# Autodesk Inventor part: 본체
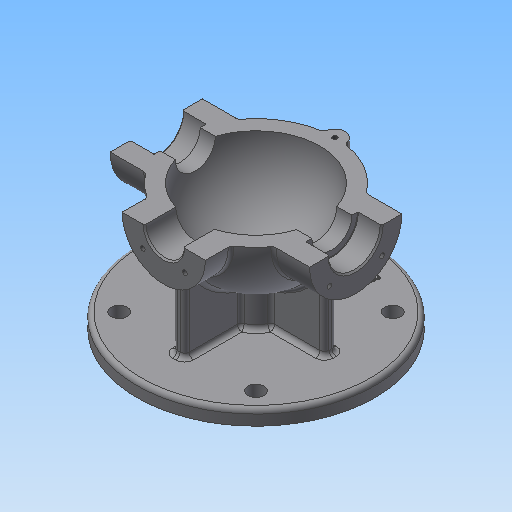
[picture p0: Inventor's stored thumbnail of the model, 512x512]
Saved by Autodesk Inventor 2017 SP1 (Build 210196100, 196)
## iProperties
Created: 2015-12
Part Number: 본체
Material: 일반
Document SubType Name: Modeling
Designer: mduedu
Density: 2.71 g/cm^3
Appearance: 기본값
Author: mduedu
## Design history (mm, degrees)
sketch "스케치1"
  geometry: L1 (-53, 0)-(53, 0); A1 r 53 centre (0, 0) between (53, 0) and (-53, 0); 2 further points
  constraints: 2 coincident, 2 end point, 2 point on circle, 1 centre point, 1 horizontal, 1 midpoint
  dimensions: "d0" = 53 radius of A1
revolve "회전1" sketch "스케치1" stored, may be unused: angle "d2" = 90 deg
feature "쉘1" dims "d11" = 10
node "작업 평면1"
sketch "스케치2"
  geometry: C1 r 31 at (0, 0); 1 further point
  constraints: 1 centre point, 1 coincident
  dimensions: "d4" = 62 diameter of C1
extrude "돌출1" join sketch "스케치2" stored distance "d5" = 10; taper "d6" = 0 deg
node "작업 평면2"
sketch "스케치3"
  geometry: C1 r 28 at (0, 0); 1 further point
  constraints: 1 centre point, 1 coincident
  dimensions: "d8" = 56 diameter of C1
extrude "돌출2" join sketch "스케치3" stored distance "d9" = 10; taper "d10" = 0 deg
hole "구멍1" diameter "d14" = 35; stored, may be unused: countersink angle "d18" = 90 deg, drill point angle "d20" = 0 deg; dims "d12" = 10, "d13" = 10, "d15" = 6, "d16" = 4, "d17" = 2, "d19" = 16
hole "구멍2" diameter "d23" = 27; stored, may be unused: countersink angle "d27" = 90 deg, drill point angle "d29" = 0 deg; dims "d21" = 10, "d22" = 10, "d24" = 6, "d25" = 4, "d26" = 2, "d28" = 16
fillet "모깎기1" dims "d30" = 0.3
hole "구멍3" diameter "d33" = 26; stored, may be unused: countersink angle "d37" = 90 deg, drill point angle "d39" = 0 deg; dims "d31" = 10, "d32" = 10, "d34" = 6, "d35" = 4, "d36" = 2, "d38" = 16
chamfer "모따기1" distance "d40" = 1; stored, may be unused: second distance "d41" = 2, angle "d42" = 45 deg
sketch "스케치4"
  geometry: L1 (0, 0)-(0, -25); L2 (0, 0)-(-17.678, -17.678); A1 r 25 centre (0, 0) between (-17.678, -17.678) and (0, -25); 1 further point
  constraints: 4 end point, 2 point on circle, 1 centre point, 1 coincident, 1 vertical
  dimensions: "d43" = 50 diameter of A1; "d47" = 45 deg angle of L1 L2
hole "구멍4" sketch "스케치4" at (-17.678, -17.678) diameter "d49" = 3.242; stored, may be unused: countersink angle "d53" = 90 deg, drill point angle "d55" = 118 deg; dims "d50" = 11, "d51" = 4, "d52" = 2, "d54" = 13
sketch "스케치5"
  geometry: L1 (0, 0)-(0, -20); L2 (0, 0)-(-14.142, -14.142); A1 r 20 centre (0, 0) between (0, -20) and (-14.142, -14.142); 2 further points
  constraints: 4 end point, 2 coincident, 2 point on circle, 1 centre point, 1 vertical
  dimensions: "d59" = 40 diameter of A1; "d65" = 45 deg angle of L1 L2
hole "구멍5" sketch "스케치5" at (-14.142, -14.142) diameter "d67" = 3.242; stored, may be unused: countersink angle "d71" = 90 deg, drill point angle "d73" = 118 deg; dims "d68" = 8, "d69" = 4, "d70" = 2, "d72" = 10
node "작업 평면3"
sketch "스케치6"
  geometry: C1 r 80 at (0, 0); 1 further point
  constraints: 1 centre point, 1 coincident
  dimensions: "d78" = 160 diameter of C1
extrude "돌출3" join sketch "스케치6" distance "d80" = 10; taper "d81" = 0 deg
sketch "스케치7"
  geometry: C1 r 15 at (0, 0); 1 further point
  constraints: 1 centre point, 1 coincident
  dimensions: "d82" = 30 diameter of C1
extrude "돌출4" join sketch "스케치7" stored distance "d84" = 10; taper "d85" = 0 deg
sketch "스케치8"
  geometry: 2 further points
  constraints: 1 coincident
hole "구멍6" sketch "스케치8" at (0, 0) diameter "d86" = 20; stored, may be unused: countersink angle "d90" = 90 deg, drill point angle "d92" = 118 deg; dims "d87" = 7, "d88" = 100, "d89" = 5, "d91" = 10
fillet "모깎기2" dims "d93" = 0.3
sketch "스케치9"
  geometry: L1 (-67, -18.5)-(-66, -17.5) reference; L2 (-66, -17.5)-(-51.3, -17.5) reference; L3 (-51, -17.2)-(-51, -13.5) reference; L4 (-51, -13.5)-(-40.826, -13.5) reference; L5 (-10, -41.821)-(-10, -80) reference; L6 (-10, -80)-(-49.7, -80) reference; L7 (-50, -80.3)-(-50, -85) reference; L8 (-50, -85)-(-80, -85) reference; L9 (-80, -85)-(-80, -75) reference; L10 (-80, -75)-(-15, -75) reference; L11 (-15, -75)-(-15, -50.833) reference; L12 (-42.988, -31)-(-67, -31) reference; L13 (-67, -31)-(-67, -18.5) reference; L14 (66, -17.5)-(67, -18.5) reference; L15 (67, -18.5)-(67, -31) reference; L16 (67, -31)-(42.988, -31) reference; L17 (15, -50.833)-(15, -75) reference; L18 (15, -75)-(80, -75) reference; L19 (80, -75)-(80, -85) reference; L20 (80, -85)-(50, -85) reference; L21 (50, -85)-(50, -80.3) reference; L22 (49.7, -80)-(10, -80) reference; L23 (10, -80)-(10, -41.821) reference; L24 (40.826, -13.5)-(51, -13.5) reference; L25 (51, -13.5)-(51, -17.2) reference; L26 (51.3, -17.5)-(66, -17.5) reference; L27 (67, 18.5)-(66, 17.5) reference; L28 (66, 17.5)-(51.3, 17.5) reference; L29 (51, 17.2)-(51, 13.5) reference; L30 (51, 13.5)-(40.826, 13.5) reference; L31 (-40.826, 13.5)-(-51, 13.5) reference; L32 (-51, 13.5)-(-51, 17.2) reference; L33 (-51.3, 17.5)-(-66, 17.5) reference; L34 (-66, 17.5)-(-67, 18.5) reference; L35 (-67, 18.5)-(-67, 31) reference; L36 (-67, 31)-(-42.988, 31) reference; L37 (42.988, 31)-(67, 31) reference; L38 (67, 31)-(67, 18.5) reference; L39 (-50, -31)-(-50, -75); A1 r 0.3 centre (-51.3, -17.2) between (-51.3, -17.5) and (-51, -17.2) reference; A2 r 43 centre (0, 0) between (-40.826, -13.5) and (-10, -41.821) reference; A3 r 0.3 centre (-49.7, -80.3) between (-49.7, -80) and (-50, -80.3) reference; A4 r 53 centre (0, 0) between (-42.988, -31) and (-15, -50.833) reference; A5 r 53 centre (0, 0) between (15, -50.833) and (42.988, -31) reference; A6 r 0.3 centre (49.7, -80.3) between (50, -80.3) and (49.7, -80) reference; A7 r 43 centre (0, 0) between (10, -41.821) and (40.826, -13.5) reference; A8 r 0.3 centre (51.3, -17.2) between (51, -17.2) and (51.3, -17.5) reference; A9 r 0.3 centre (51.3, 17.2) between (51.3, 17.5) and (51, 17.2) reference; A10 r 43 centre (0, 0) between (40.826, 13.5) and (-40.826, 13.5) reference; A11 r 0.3 centre (-51.3, 17.2) between (-51, 17.2) and (-51.3, 17.5) reference; A12 r 53 centre (0, 0) between (42.988, 31) and (-42.988, 31) reference; 1 further point
  constraints: 2 end point, 2 point on line
  dimensions: "d173" = 30 distance from line of L39.end L9; "d174" = 90 deg angle of L10 L39
feature "리브1" sketch "스케치9" dims "d96" = 1, "d97" = 8, "d98" = 0, "d99" = 0, "d100" = 1, "d101" = 1
sketch "스케치14"
  geometry: L1 (-14, 62)-(-13, 61) reference; L2 (-13, 61)-(-13, 40.988) reference; L3 (-41.821, 10)-(-80, 10) reference; L4 (-80, 10)-(-80, 49.7) reference; L5 (-80.3, 50)-(-85, 50) reference; L6 (-85, 50)-(-85, 80) reference; L7 (-85, 80)-(-75, 80) reference; L8 (-75, 80)-(-75, 15) reference; L9 (-75, 15)-(-50.833, 15) reference; L10 (-28, 45)-(-28, 62) reference; L11 (-28, 62)-(-14, 62) reference; L12 (13, 61)-(14, 62) reference; L13 (14, 62)-(28, 62) reference; L14 (28, 62)-(28, 45) reference; L15 (-50.833, -15)-(-75, -15) reference; L16 (-75, -15)-(-75, -80) reference; L17 (-75, -80)-(-85, -80) reference; L18 (-85, -80)-(-85, -50) reference; L19 (-85, -50)-(-80.3, -50) reference; L20 (-80, -49.7)-(-80, -10) reference; L21 (-80, -10)-(-41.821, -10) reference; L22 (13, 40.988)-(13, 61) reference; L23 (-28, 52)-(-75, 52); A1 r 43 centre (0, 0) between (-13, 40.988) and (-41.821, 10) reference; A2 r 0.3 centre (-80.3, 49.7) between (-80, 49.7) and (-80.3, 50) reference; A3 r 53 centre (0, 0) between (-28, 45) and (-50.833, 15) reference; A4 r 53 centre (0, 0) between (0, -53) and (28, 45) reference; A5 r 53 centre (0, 0) between (-50.833, -15) and (0, -53) reference; A6 r 0.3 centre (-80.3, -49.7) between (-80.3, -50) and (-80, -49.7) reference; A7 r 43 centre (0, 0) between (-41.821, -10) and (0, -43) reference; A8 r 43 centre (0, 0) between (0, -43) and (13, 40.988) reference; 1 further point
  constraints: 2 end point, 2 point on line
  dimensions: "d175" = 28 distance of L7.end L23.end; "d176" = 90 deg angle of L8 L23
feature "리브2" sketch "스케치14" dims "d153" = 1, "d154" = 8, "d155" = 0, "d156" = 0, "d157" = 1, "d158" = 1
sketch "스케치10"
  geometry: L1 (0, 0)-(0, -65); L2 (0, 0)-(-45.962, -45.962); A1 r 65 centre (0, 0) between (0, -65) and (-45.962, -45.962); 2 further points
  constraints: 4 end point, 2 coincident, 2 point on circle, 1 centre point, 1 vertical
  dimensions: "d105" = 130 diameter of A1; "d107" = 45 deg angle of L1 L2
hole "구멍7" sketch "스케치10" at (-45.962, -45.962) diameter "d109" = 11; stored, may be unused: countersink angle "d113" = 90 deg, drill point angle "d115" = 118 deg; dims "d110" = 7, "d111" = 18, "d112" = 4, "d114" = 10
fillet "모깎기3" dims "d120" = 3
fillet "모깎기4" dims "d121" = 3, "d122" = 3
fillet "모깎기5" dims "d123" = 3
fillet "모깎기6" dims "d124" = 3
sketch "스케치11"
  geometry: C1 r 80 at (0, 0) reference; C2 r 65 at (0, 0)
  constraints: 1 centre point, 1 coincident, 1 other
  dimensions: "d161" = 130 diameter of C2
feature "엠보싱1" sketch "스케치11" dims "d11" = 10, "d125" = 0.5, "d126" = 0
sketch "스케치12"
  geometry: L1 (0, 100)-(0, -100); L2 (0, 100)-(100, 100); L3 (100, 100)-(100, -100); L4 (100, -100)-(0, -100); 2 further points
  constraints: 8 end point, 3 perpendicular, 1 coincident, 1 midpoint, 1 vertical
  dimensions: "d127" = 200 distance of L2.end L3.end; "d129" = 100 distance between parallel lines of L1 L3
extrude "돌출5" cut sketch "스케치12" stored distance "d130" = 10; taper "d131" = 0 deg
sketch "스케치13"
  geometry: C1 r 7 at (0, 53); A1 r 53 centre (0, 0) between (42.113, 32.179) and (-42.113, 32.179) reference; 1 further point
  constraints: 1 centre point, 1 point on circle
  dimensions: "d132" = 14 diameter of C1
extrude "돌출6" join sketch "스케치13" distance "d134" = 15; taper "d135" = 0 deg
hole "구멍8" diameter "d139" = 3.242; stored, may be unused: countersink angle "d143" = 90 deg, drill point angle "d145" = 118 deg; dims "d140" = 8, "d141" = 4, "d142" = 2, "d144" = 10, "d148" = 10, "d149" = 10
fillet "모깎기7" dims "d146" = 3
fillet "모깎기8" dims "d147" = 3
node "솔리드1"
mirror "대칭1"
mirror "대칭2"
pattern_circular "원형 패턴1" dims angle "d57" = 360 deg
mirror "대칭3"
pattern_circular "원형 패턴2" dims angle "d75" = 360 deg
mirror "대칭4"
pattern_circular "원형 패턴4" dims angle "d118" = 360 deg
node "절단 모서리 투영1"
node "절단 모서리 투영2"
other parameters: "d3" = 67, "d7" = 62, "d77" = -85
